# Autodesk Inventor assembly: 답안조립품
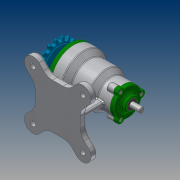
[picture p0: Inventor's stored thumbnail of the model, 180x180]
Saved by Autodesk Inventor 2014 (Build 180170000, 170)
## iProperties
Created: 2017-03
Part Number: 답안조립품
Document SubType Name: Assembly
Designer: Administrator
Author: Administrator
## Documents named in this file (14)
- C:\Users\Administrator\Desktop\470308V1009\470308V1009\답안조립품.iam
- C:\Users\Administrator\Desktop\470308V1009\본체.ipt
- C:\Users\Administrator\Desktop\470308V1009\470308V1009\뒤커버.ipt
- C:\Users\Administrator\Desktop\470308V1009\470308V1009\베어링-6200.ipt
- C:\Users\Administrator\Desktop\470308V1009\470308V1009\베어링-6203.ipt
- C:\Users\Administrator\Desktop\470308V1009\470308V1009\볼트 M4 x 12.ipt
- C:\Users\Administrator\Desktop\470308V1009\470308V1009\볼트 M5 x 10.ipt
- 볼트 M5 x 10.ipt
- C:\Users\Administrator\Desktop\470308V1009\470308V1009\스프로킷.ipt
- C:\Users\Administrator\Desktop\470308V1009\470308V1009\앞커버.ipt
- C:\Users\Administrator\Desktop\470308V1009\470308V1009\오일 실 10 20 7.ipt
- C:\Users\Administrator\Desktop\470308V1009\470308V1009\오일 실 17 30 8.ipt
- C:\Users\Administrator\Desktop\470308V1009\470308V1009\축.ipt
- C:\Users\Administrator\Desktop\470308V1009\470308V1009\키5x5.ipt
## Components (9 placed, 1 different names)
1. ISO 4762 M4 x 12:1 — 각도:5
2. ISO 4762 M4 x 12:3
3. ISO 4762 M4 x 12:4
4. ISO 4762 M4 x 12:2 — 각도:6
5. ISO 4762 M4 x 12:5
6. ISO 4762 M4 x 12:6
7. ISO 4762 M4 x 12:7
8. ISO 4762 M4 x 12:8
9. ISO 4762 M4 x 12:9
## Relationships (2: Angle 2)
- 각도:5 [Angle]: ISO 4762 M4 x 12:1
- 각도:6 [Angle]: ISO 4762 M4 x 12:2
